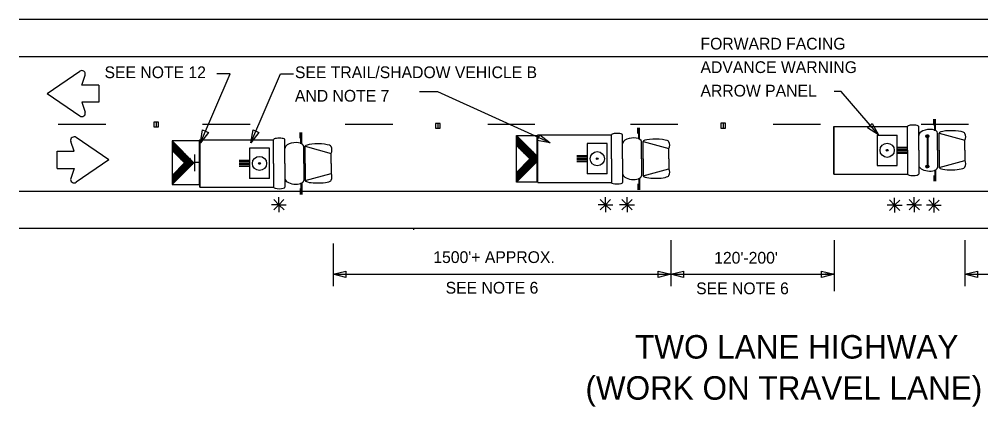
# Model space of a CAD drawing. Extents: x 1373848 to 1374003, y 380642 to 381248.
# Drawn here: x 1373848.14 to 1373897.19, y 381053.14 to 381072.93 of the extents above; entities that cross this region are included whole.
import ezdxf

# ---------------------------------------------------------------- set-up
doc = ezdxf.new("R2010")
doc.units = 0
doc.layers.add('Level 1', color=7, linetype='Continuous')
doc.layers.add('Working Level 1', color=7, linetype='Continuous')

msp = doc.modelspace()

# ---------------------------------------------------------------- linework, layer by layer
at = {"layer": 'Level 1'}
for points in [[(1373857.393, 381066.621), (1373858.897, 381070.147), (1373858.229, 381070.147)], [(1373859.965, 381066.621), (1373861.47, 381070.147), (1373862.139, 381070.147)], [(1373875.22, 381066.621), (1373869.494, 381069.227), (1373868.561, 381069.227)]]:
    msp.add_lwpolyline(points, dxfattribs=at)
at = {"layer": 'Working Level 1'}
for p, q in [((1373848.144, 381072.933), (1373928.119, 381072.933)), ((1373848.144, 381071.021), (1373928.119, 381071.021)), ((1373849.571, 381069.138), (1373851.238, 381070.281)), ((1373851.343, 381069.574), (1373851.506, 381070.082)), ((1373852.211, 381069.574), (1373851.343, 381069.574)), ((1373852.211, 381069.574), (1373852.211, 381068.701)), ((1373849.571, 381069.138), (1373851.238, 381067.994)), ((1373852.211, 381068.701), (1373851.343, 381068.701)), ((1373851.343, 381068.701), (1373851.506, 381068.194)), ((1373855.256, 381067.682), (1373855.013, 381067.682)), ((1373855.013, 381067.682), (1373855.013, 381067.439)), ((1373855.135, 381067.682), (1373855.135, 381067.439)), ((1373855.256, 381067.439), (1373855.256, 381067.682)), ((1373869.624, 381067.607), (1373869.381, 381067.607)), ((1373869.381, 381067.607), (1373869.381, 381067.364)), ((1373869.503, 381067.607), (1373869.502, 381067.364)), ((1373869.624, 381067.364), (1373869.624, 381067.607)), ((1373884.168, 381067.621), (1373883.925, 381067.621)), ((1373883.925, 381067.621), (1373883.925, 381067.378)), ((1373884.047, 381067.621), (1373884.046, 381067.378)), ((1373884.168, 381067.378), (1373884.168, 381067.621)), ((1373889.697, 381067.454), (1373893.452, 381067.454)), ((1373889.697, 381065.028), (1373889.697, 381067.454)), ((1373889.697, 381067.454), (1373889.697, 381065.029)), ((1373893.452, 381066.241), (1373893.452, 381067.454)), ((1373894.027, 381066.241), (1373894.027, 381067.454)), ((1373894.803, 381067.527), (1373894.803, 381067.823)), ((1373894.85, 381067.241), (1373894.85, 381067.823)), ((1373894.889, 381067.241), (1373894.889, 381067.823)), ((1373855.013, 381067.439), (1373855.256, 381067.439)), ((1373862.469, 381066.856), (1373862.469, 381067.153)), ((1373862.516, 381066.57), (1373862.516, 381067.153)), ((1373862.556, 381066.57), (1373862.556, 381067.153)), ((1373869.381, 381067.364), (1373869.624, 381067.364)), ((1373873.508, 381066.995), (1373874.544, 381065.96)), ((1373874.594, 381067.024), (1373878.349, 381067.024)), ((1373874.594, 381064.598), (1373874.594, 381067.024)), ((1373878.349, 381065.811), (1373878.349, 381067.024)), ((1373878.924, 381065.811), (1373878.924, 381067.024)), ((1373879.7, 381067.096), (1373879.7, 381067.393)), ((1373879.747, 381066.811), (1373879.747, 381067.393)), ((1373879.786, 381066.811), (1373879.786, 381067.393)), ((1373883.925, 381067.378), (1373884.168, 381067.378)), ((1373891.903, 381067.018), (1373892.929, 381067.018)), ((1373891.903, 381067.018), (1373891.903, 381065.465)), ((1373892.929, 381065.465), (1373892.929, 381067.018)), ((1373894.394, 381066.979), (1373894.394, 381066.979)), ((1373894.482, 381067.029), (1373894.482, 381067.029)), ((1373894.991, 381066.241), (1373894.991, 381067.115)), ((1373895.071, 381067.115), (1373896.384, 381066.756)), ((1373895.071, 381066.241), (1373895.071, 381067.115)), ((1373850.939, 381066.188), (1373850.776, 381066.696)), ((1373852.711, 381065.752), (1373851.044, 381066.896)), ((1373855.938, 381066.719), (1373857.056, 381065.602)), ((1373857.364, 381066.784), (1373857.364, 381064.358)), ((1373857.364, 381066.783), (1373861.119, 381066.783)), ((1373857.364, 381064.358), (1373857.364, 381066.783)), ((1373861.119, 381065.571), (1373861.119, 381066.783)), ((1373861.694, 381065.571), (1373861.694, 381066.783)), ((1373873.508, 381066.478), (1373874.191, 381065.797)), ((1373878.142, 381066.587), (1373877.116, 381066.587)), ((1373877.116, 381066.587), (1373877.116, 381065.035)), ((1373878.142, 381065.035), (1373878.142, 381066.587)), ((1373879.888, 381065.811), (1373879.888, 381066.685)), ((1373879.968, 381066.685), (1373881.281, 381066.326)), ((1373879.968, 381065.811), (1373879.968, 381066.685)), ((1373894.456, 381066.944), (1373894.456, 381065.438)), ((1373894.46, 381066.944), (1373894.46, 381065.438)), ((1373894.464, 381066.944), (1373894.464, 381065.438)), ((1373894.472, 381066.944), (1373894.472, 381065.438)), ((1373894.484, 381066.944), (1373894.484, 381065.438)), ((1373896.384, 381066.241), (1373896.384, 381066.756)), ((1373850.071, 381065.315), (1373850.071, 381066.188)), ((1373850.071, 381066.188), (1373850.939, 381066.188)), ((1373855.938, 381066.234), (1373856.579, 381065.595)), ((1373857.094, 381065.182), (1373857.094, 381066.023)), ((1373860.912, 381066.347), (1373859.886, 381066.347)), ((1373859.886, 381066.347), (1373859.886, 381064.794)), ((1373860.912, 381064.794), (1373860.912, 381066.347)), ((1373862.657, 381065.571), (1373862.657, 381066.444)), ((1373862.737, 381066.444), (1373864.05, 381066.085)), ((1373862.737, 381065.571), (1373862.737, 381066.444)), ((1373864.05, 381065.571), (1373864.05, 381066.085)), ((1373881.281, 381065.811), (1373881.281, 381066.326)), ((1373892.929, 381066.397), (1373893.452, 381066.397)), ((1373892.929, 381066.319), (1373893.452, 381066.319)), ((1373892.929, 381066.241), (1373893.452, 381066.241)), ((1373892.929, 381066.164), (1373893.452, 381066.164)), ((1373892.929, 381066.086), (1373893.452, 381066.086)), ((1373893.452, 381066.241), (1373893.452, 381065.029)), ((1373894.027, 381066.241), (1373894.027, 381065.029)), ((1373894.991, 381066.241), (1373894.991, 381065.368)), ((1373895.071, 381066.241), (1373895.071, 381065.368)), ((1373896.384, 381066.241), (1373896.384, 381065.727)), ((1373852.711, 381065.752), (1373851.044, 381064.608)), ((1373855.938, 381064.956), (1373856.579, 381065.595)), ((1373855.944, 381064.489), (1373857.056, 381065.602)), ((1373857.327, 381065.622), (1373857.087, 381065.622)), ((1373859.886, 381065.726), (1373859.363, 381065.726)), ((1373859.886, 381065.648), (1373859.363, 381065.648)), ((1373859.886, 381065.571), (1373859.363, 381065.571)), ((1373859.886, 381065.493), (1373859.363, 381065.493)), ((1373861.119, 381065.571), (1373861.119, 381064.358)), ((1373861.694, 381065.571), (1373861.694, 381064.358)), ((1373862.657, 381065.571), (1373862.657, 381064.697)), ((1373862.737, 381065.571), (1373862.737, 381064.697)), ((1373864.05, 381065.571), (1373864.05, 381065.056)), ((1373873.508, 381065.115), (1373874.191, 381065.797)), ((1373873.514, 381064.617), (1373874.539, 381065.643)), ((1373877.116, 381065.966), (1373876.593, 381065.966)), ((1373877.116, 381065.889), (1373876.593, 381065.889)), ((1373877.116, 381065.811), (1373876.593, 381065.811)), ((1373877.116, 381065.733), (1373876.593, 381065.733)), ((1373877.116, 381065.656), (1373876.593, 381065.656)), ((1373878.349, 381065.811), (1373878.349, 381064.599)), ((1373878.924, 381065.811), (1373878.924, 381064.599)), ((1373879.888, 381065.811), (1373879.888, 381064.938)), ((1373879.968, 381065.811), (1373879.968, 381064.938)), ((1373881.281, 381065.811), (1373881.281, 381065.296)), ((1373895.071, 381065.368), (1373896.384, 381065.727)), ((1373850.071, 381065.315), (1373850.939, 381065.315)), ((1373850.939, 381065.315), (1373850.776, 381064.808)), ((1373859.886, 381065.415), (1373859.363, 381065.415)), ((1373862.737, 381064.697), (1373864.05, 381065.056)), ((1373878.142, 381065.035), (1373877.116, 381065.035)), ((1373879.968, 381064.938), (1373881.281, 381065.296)), ((1373889.697, 381065.029), (1373893.452, 381065.029)), ((1373891.903, 381065.465), (1373892.929, 381065.465)), ((1373894.398, 381065.425), (1373894.398, 381065.425)), ((1373894.486, 381065.476), (1373894.486, 381065.476)), ((1373894.85, 381065.242), (1373894.85, 381064.659)), ((1373894.889, 381065.242), (1373894.889, 381064.659)), ((1373860.912, 381064.794), (1373859.886, 381064.794)), ((1373862.516, 381064.571), (1373862.516, 381063.988)), ((1373862.556, 381064.571), (1373862.556, 381063.988)), ((1373874.594, 381064.599), (1373878.349, 381064.599)), ((1373879.7, 381064.526), (1373879.7, 381064.229)), ((1373879.747, 381064.811), (1373879.747, 381064.229)), ((1373879.786, 381064.811), (1373879.786, 381064.229)), ((1373894.803, 381064.956), (1373894.803, 381064.659)), ((1373848.144, 381064.151), (1373928.119, 381064.151)), ((1373857.364, 381064.358), (1373861.119, 381064.358)), ((1373862.469, 381064.285), (1373862.469, 381063.988)), ((1373861.389, 381063.464), (1373861.123, 381063.73)), ((1373861.383, 381063.459), (1373861.649, 381063.725)), ((1373861.389, 381063.464), (1373861.389, 381063.84)), ((1373878.049, 381063.464), (1373877.783, 381063.73)), ((1373878.042, 381063.459), (1373878.309, 381063.725)), ((1373878.049, 381063.464), (1373878.049, 381063.84)), ((1373879.147, 381063.464), (1373878.881, 381063.73)), ((1373879.14, 381063.459), (1373879.407, 381063.725)), ((1373879.147, 381063.464), (1373879.147, 381063.84)), ((1373892.799, 381063.44), (1373892.533, 381063.706)), ((1373892.792, 381063.435), (1373893.059, 381063.701)), ((1373892.799, 381063.44), (1373892.799, 381063.816)), ((1373893.801, 381063.464), (1373893.535, 381063.73)), ((1373893.795, 381063.459), (1373894.061, 381063.725)), ((1373893.801, 381063.464), (1373893.801, 381063.84)), ((1373894.804, 381063.44), (1373894.538, 381063.706)), ((1373894.797, 381063.435), (1373895.064, 381063.701)), ((1373894.804, 381063.44), (1373894.804, 381063.816)), ((1373861.389, 381063.464), (1373861.013, 381063.464)), ((1373861.389, 381063.464), (1373861.123, 381063.198)), ((1373861.389, 381063.464), (1373861.655, 381063.198)), ((1373861.389, 381063.464), (1373861.389, 381063.088)), ((1373861.389, 381063.464), (1373861.765, 381063.464)), ((1373878.049, 381063.464), (1373877.672, 381063.464)), ((1373878.049, 381063.464), (1373877.783, 381063.198)), ((1373878.049, 381063.464), (1373878.315, 381063.198)), ((1373878.049, 381063.464), (1373878.049, 381063.088)), ((1373878.049, 381063.464), (1373878.425, 381063.464)), ((1373879.147, 381063.464), (1373878.77, 381063.464)), ((1373879.147, 381063.464), (1373878.881, 381063.198)), ((1373879.147, 381063.464), (1373879.413, 381063.198)), ((1373879.147, 381063.464), (1373879.147, 381063.088)), ((1373879.147, 381063.464), (1373879.523, 381063.464)), ((1373892.799, 381063.44), (1373892.422, 381063.44)), ((1373892.799, 381063.44), (1373892.533, 381063.174)), ((1373892.799, 381063.44), (1373893.065, 381063.174)), ((1373892.799, 381063.44), (1373892.799, 381063.064)), ((1373892.799, 381063.44), (1373893.175, 381063.44)), ((1373893.801, 381063.464), (1373893.425, 381063.464)), ((1373893.801, 381063.464), (1373893.535, 381063.198)), ((1373893.801, 381063.464), (1373894.067, 381063.198)), ((1373893.801, 381063.464), (1373893.801, 381063.088)), ((1373893.801, 381063.464), (1373894.177, 381063.464)), ((1373894.804, 381063.44), (1373894.427, 381063.44)), ((1373894.804, 381063.44), (1373894.538, 381063.174)), ((1373894.804, 381063.44), (1373895.07, 381063.174)), ((1373894.804, 381063.44), (1373894.804, 381063.064)), ((1373894.804, 381063.44), (1373895.18, 381063.44)), ((1373848.144, 381062.263), (1373928.119, 381062.263)), ((1373868.292, 381062.203), (1373868.243, 381062.203)), ((1373881.384, 381061.657), (1373881.384, 381059.304)), ((1373889.714, 381061.657), (1373889.714, 381059.04)), ((1373896.372, 381061.657), (1373896.372, 381059.304)), ((1373864.158, 381061.484), (1373864.158, 381059.304)), ((1373864.158, 381059.911), (1373881.384, 381059.911)), ((1373864.158, 381059.911), (1373864.734, 381059.911)), ((1373881.384, 381059.911), (1373881.269, 381059.911)), ((1373881.384, 381059.911), (1373881.839, 381059.911)), ((1373881.384, 381059.911), (1373889.714, 381059.911)), ((1373889.714, 381059.911), (1373889.262, 381059.911)), ((1373896.372, 381059.911), (1373896.827, 381059.911)), ((1373896.382, 381059.911), (1373904.711, 381059.911))]:
    msp.add_line(p, q, dxfattribs=at)
for points in [[(1373891.983, 381067.031), (1373890.073, 381069.249), (1373889.709, 381069.249)], [(1373850.129, 381067.575), (1373852.554, 381067.575)], [(1373857.493, 381067.575), (1373859.918, 381067.575)], [(1373864.768, 381067.575), (1373867.194, 381067.575)], [(1373872.044, 381067.575), (1373874.439, 381067.575)], [(1373879.319, 381067.575), (1373881.745, 381067.575)], [(1373886.595, 381067.575), (1373889.02, 381067.575)], [(1373894.144, 381067.575), (1373896.57, 381067.575)], [(1373894.394, 381066.979), (1373894.442, 381066.894)], [(1373894.4, 381066.997), (1373894.461, 381066.89)], [(1373894.409, 381067.01), (1373894.477, 381066.892)], [(1373894.42, 381067.02), (1373894.492, 381066.896)], [(1373894.432, 381067.029), (1373894.504, 381066.903)], [(1373894.446, 381067.033), (1373894.515, 381066.913)], [(1373894.461, 381067.036), (1373894.525, 381066.925)], [(1373894.48, 381067.034), (1373894.532, 381066.942)], [(1373894.501, 381067.026), (1373894.536, 381066.965)], [(1373855.938, 381066.667), (1373856.528, 381065.645)], [(1373855.938, 381066.579), (1373856.411, 381065.759)], [(1373855.938, 381066.491), (1373856.294, 381065.874)], [(1373855.988, 381066.67), (1373856.769, 381065.316)], [(1373856.107, 381066.55), (1373856.801, 381065.348)], [(1373873.508, 381066.94), (1373874.137, 381065.85)], [(1373873.508, 381066.847), (1373874.012, 381065.972)], [(1373873.508, 381066.752), (1373873.888, 381066.094)], [(1373873.508, 381066.659), (1373873.763, 381066.216)], [(1373873.508, 381066.565), (1373873.639, 381066.338)], [(1373873.508, 381066.471), (1373873.514, 381066.46)], [(1373873.56, 381066.943), (1373874.394, 381065.499)], [(1373873.688, 381066.815), (1373874.428, 381065.533)], [(1373873.816, 381066.687), (1373874.463, 381065.568)], [(1373873.944, 381066.559), (1373874.497, 381065.602)], [(1373894.392, 381066.952), (1373894.418, 381066.907)], [(1373855.938, 381066.403), (1373856.177, 381065.989)], [(1373855.938, 381066.315), (1373856.061, 381066.103)], [(1373855.938, 381066.227), (1373855.944, 381066.218)], [(1373856.227, 381066.43), (1373856.834, 381065.38)], [(1373856.347, 381066.31), (1373856.866, 381065.412)], [(1373856.466, 381066.19), (1373856.898, 381065.444)], [(1373856.587, 381066.07), (1373856.931, 381065.475)], [(1373874.072, 381066.432), (1373874.531, 381065.636)], [(1373874.2, 381066.304), (1373874.54, 381065.715)], [(1373874.328, 381066.176), (1373874.541, 381065.807)], [(1373874.455, 381066.049), (1373874.543, 381065.897)], [(1373856.5, 381065.517), (1373856.672, 381065.219)], [(1373856.532, 381065.55), (1373856.705, 381065.252)], [(1373856.565, 381065.582), (1373856.737, 381065.284)], [(1373856.707, 381065.951), (1373856.964, 381065.505)], [(1373856.827, 381065.832), (1373856.994, 381065.542)], [(1373856.937, 381065.723), (1373857.024, 381065.573)], [(1373873.901, 381065.508), (1373874.084, 381065.191)], [(1373873.936, 381065.543), (1373874.119, 381065.225)], [(1373873.97, 381065.577), (1373874.153, 381065.26)], [(1373874.004, 381065.611), (1373874.188, 381065.294)], [(1373874.038, 381065.646), (1373874.222, 381065.328)], [(1373874.073, 381065.68), (1373874.256, 381065.362)], [(1373874.108, 381065.714), (1373874.29, 381065.396)], [(1373874.141, 381065.748), (1373874.325, 381065.431)], [(1373874.176, 381065.783), (1373874.36, 381065.465)], [(1373855.985, 381065.004), (1373856.157, 381064.706)], [(1373856.017, 381065.035), (1373856.188, 381064.739)], [(1373856.05, 381065.068), (1373856.221, 381064.77)], [(1373856.081, 381065.1), (1373856.253, 381064.803)], [(1373856.114, 381065.132), (1373856.285, 381064.835)], [(1373856.146, 381065.164), (1373856.318, 381064.867)], [(1373856.178, 381065.196), (1373856.35, 381064.899)], [(1373856.211, 381065.228), (1373856.382, 381064.931)], [(1373856.243, 381065.261), (1373856.415, 381064.963)], [(1373856.275, 381065.293), (1373856.447, 381064.995)], [(1373856.306, 381065.325), (1373856.479, 381065.027)], [(1373856.339, 381065.357), (1373856.512, 381065.059)], [(1373856.371, 381065.389), (1373856.543, 381065.092)], [(1373856.403, 381065.421), (1373856.576, 381065.123)], [(1373856.436, 381065.454), (1373856.608, 381065.155)], [(1373856.468, 381065.486), (1373856.64, 381065.188)], [(1373873.508, 381065.065), (1373873.672, 381064.78)], [(1373873.524, 381065.131), (1373873.706, 381064.815)], [(1373873.558, 381065.166), (1373873.741, 381064.849)], [(1373873.592, 381065.199), (1373873.775, 381064.884)], [(1373873.627, 381065.234), (1373873.81, 381064.917)], [(1373873.661, 381065.268), (1373873.844, 381064.952)], [(1373873.695, 381065.303), (1373873.878, 381064.986)], [(1373873.729, 381065.337), (1373873.912, 381065.02)], [(1373873.764, 381065.371), (1373873.947, 381065.054)], [(1373873.799, 381065.406), (1373873.981, 381065.088)], [(1373873.833, 381065.44), (1373874.016, 381065.123)], [(1373873.867, 381065.474), (1373874.05, 381065.157)], [(1373894.396, 381065.399), (1373894.423, 381065.353)], [(1373894.398, 381065.425), (1373894.447, 381065.341)], [(1373894.404, 381065.444), (1373894.465, 381065.337)], [(1373894.413, 381065.457), (1373894.481, 381065.339)], [(1373894.424, 381065.467), (1373894.496, 381065.343)], [(1373894.436, 381065.475), (1373894.509, 381065.35)], [(1373894.45, 381065.479), (1373894.52, 381065.359)], [(1373894.465, 381065.483), (1373894.529, 381065.372)], [(1373894.484, 381065.481), (1373894.537, 381065.388)], [(1373894.505, 381065.473), (1373894.54, 381065.411)], [(1373855.938, 381064.909), (1373856.092, 381064.642)], [(1373855.938, 381064.821), (1373856.06, 381064.61)], [(1373855.938, 381064.733), (1373856.028, 381064.578)], [(1373855.938, 381064.645), (1373855.995, 381064.546)], [(1373855.938, 381064.557), (1373855.963, 381064.515)], [(1373855.953, 381064.971), (1373856.124, 381064.675)], [(1373873.508, 381064.971), (1373873.638, 381064.746)], [(1373873.508, 381064.877), (1373873.603, 381064.712)], [(1373873.508, 381064.783), (1373873.569, 381064.678)], [(1373873.508, 381064.69), (1373873.534, 381064.644)]]:
    msp.add_lwpolyline(points, dxfattribs=at)
for points in [[(1373891.645, 381067.61), (1373891.983, 381067.031), (1373891.412, 381067.382)], [(1373857.797, 381067.155), (1373857.393, 381066.621), (1373857.498, 381067.282)], [(1373860.37, 381067.155), (1373859.965, 381066.621), (1373860.071, 381067.282)], [(1373874.546, 381064.617), (1373873.508, 381064.617), (1373873.508, 381066.995), (1373874.546, 381066.995)], [(1373874.696, 381067.038), (1373875.22, 381066.621), (1373874.561, 381066.742)], [(1373855.938, 381066.719), (1373855.938, 381064.489), (1373857.332, 381064.489), (1373857.332, 381066.719)], [(1373864.808, 381059.748), (1373864.158, 381059.911), (1373864.808, 381060.073)], [(1373880.734, 381060.073), (1373881.384, 381059.911), (1373880.734, 381059.748)], [(1373882.034, 381059.748), (1373881.384, 381059.911), (1373882.034, 381060.073)], [(1373889.064, 381060.073), (1373889.714, 381059.911), (1373889.064, 381059.748)], [(1373897.022, 381059.748), (1373896.372, 381059.911), (1373897.022, 381060.073)]]:
    msp.add_lwpolyline(points, close=True, dxfattribs=at)
for centre, radius in [((1373894.464, 381066.963), 0.0728), ((1373892.416, 381066.241), 0.362), ((1373877.629, 381065.811), 0.362), ((1373892.416, 381066.241), 0.0451), ((1373860.399, 381065.57), 0.362), ((1373860.399, 381065.57), 0.0451), ((1373877.629, 381065.811), 0.0451), ((1373894.468, 381065.41), 0.0728)]:
    msp.add_circle(centre, radius, dxfattribs=at)
for centre, radius, start, end in [((1373851.338, 381070.135), 0.177, 342.1824, 124.4455), ((1373851.338, 381068.14), 0.177, 235.5545, 17.8176), ((1373896.062, 381066.927), 0.364, 331.8801, 28.1199), ((1373850.944, 381066.75), 0.177, 55.5545, 197.8176), ((1373880.959, 381066.498), 0.364, 331.8801, 28.1199), ((1373863.729, 381066.257), 0.364, 331.8801, 28.1199), ((1373896.062, 381065.555), 0.364, 331.8801, 28.1199), ((1373863.729, 381064.884), 0.364, 331.8801, 28.1199), ((1373880.959, 381065.125), 0.364, 331.8801, 28.1199), ((1373850.944, 381064.754), 0.177, 162.1824, 304.4455)]:
    msp.add_arc(centre, radius, start, end, dxfattribs=at)
for centre, major_axis, ratio, start_param, end_param in [((1373893.739, 381067.454), (0.288, 0), 0.269913, 0, 3.141593), ((1373878.637, 381067.024), (0.288, 0), 0.269913, 0, 3.141593), ((1373894.509, 381067.055), (0.482, 0.06), 0.503092, 0, 3.141593), ((1373895.727, 381067.107), (0.656, -0.008), 0.2034, 0, 3.141593), ((1373861.406, 381066.783), (0.288, 0), 0.269913, 0, 3.141593), ((1373862.176, 381066.384), (0.482, 0.06), 0.503092, 0, 3.141593), ((1373863.394, 381066.436), (0.656, -0.008), 0.2034, 0, 3.141593), ((1373879.406, 381066.625), (0.482, 0.06), 0.503092, 0, 3.141593), ((1373880.624, 381066.677), (0.656, -0.008), 0.2034, 0, 3.141593), ((1373879.406, 381064.997), (0.482, -0.06), 0.503092, 3.141593, 6.283185), ((1373893.739, 381065.029), (0.288, 0), 0.269913, 3.141593, 6.283185), ((1373894.509, 381065.427), (0.482, -0.06), 0.503092, 3.141593, 6.283185), ((1373895.727, 381065.375), (0.656, 0.008), 0.2034, 3.141593, 6.283185), ((1373862.176, 381064.757), (0.482, -0.06), 0.503092, 3.141593, 6.283185), ((1373863.394, 381064.704), (0.656, 0.008), 0.2034, 3.141593, 6.283185), ((1373878.637, 381064.599), (0.288, 0), 0.269913, 3.141593, 6.283185), ((1373880.624, 381064.945), (0.656, 0.008), 0.2034, 3.141593, 6.283185), ((1373861.406, 381064.358), (0.288, 0), 0.269913, 3.141593, 6.283185)]:
    msp.add_ellipse(centre, major_axis=major_axis, ratio=ratio, start_param=start_param, end_param=end_param, dxfattribs=at)

# ---------------------------------------------------------------- texts
for s, height, p in [('FORWARD FACING', 0.6, (1373882.896, 381071.385)), ('SEE NOTE 12 ', 0.6, (1373852.495, 381069.924)), ('SEE TRAIL/SHADOW VEHICLE B', 0.6, (1373862.208, 381069.924)), ('ADVANCE WARNING ', 0.6, (1373882.896, 381070.185)), ('ARROW PANEL', 0.6, (1373882.896, 381068.985)), ('AND NOTE 7 ', 0.6, (1373862.208, 381068.724)), ("1500'+ APPROX.", 0.6, (1373869.266, 381060.485)), ("120'-200'", 0.6, (1373883.593, 381060.453)), ('SEE NOTE 6', 0.6, (1373869.896, 381058.923)), ('SEE NOTE 6', 0.6, (1373882.674, 381058.891)), ('TWO LANE HIGHWAY', 1.2, (1373879.56, 381055.606)), ('(WORK ON TRAVEL LANE)', 1.2, (1373877.027, 381053.506))]:
    msp.add_text(s, height=height, dxfattribs=at).set_placement(p)

doc.saveas('drawing.dxf')
